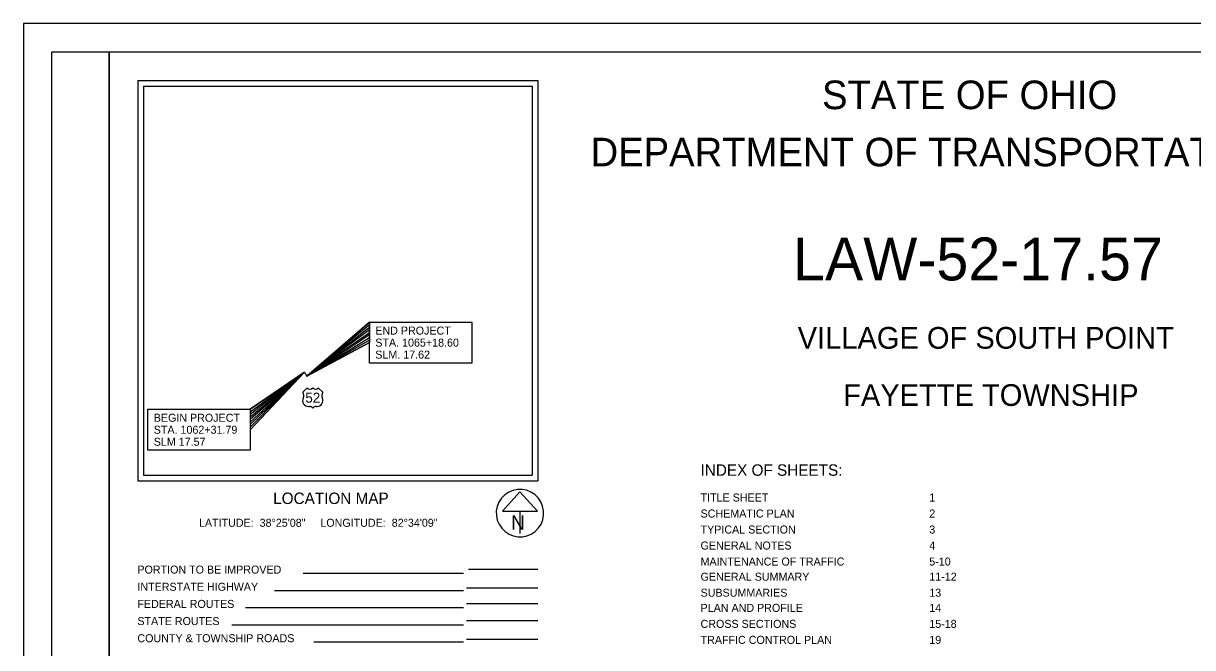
# Model space of a CAD drawing. Extents: x 0 to 34, y 0 to 22.
# Drawn here: x 0 to 20.45, y 11.08 to 22 of the extents above; entities that cross this region are included whole.
import ezdxf

# ---------------------------------------------------------------- set-up
doc = ezdxf.new("R2010")
doc.units = 0
for name, color, linetype in [('GM_X_County_Road', 7, 'Continuous'), ('GM_X_Minor_River', 7, 'Continuous'), ('SH_Border', 7, 'Continuous'), ('SH_Cut_Line', 7, 'Continuous'), ('SH_Data', 7, 'Continuous'), ('SH_Text', 7, 'Continuous')]:
    doc.layers.add(name, color=color, linetype=linetype)

msp = doc.modelspace()

# ---------------------------------------------------------------- linework, layer by layer
at = {"layer": 'GM_X_County_Road'}
for p, q in [((4.958, 15.623), (4.885, 15.55)), ((5.237, 15.55), (5.164, 15.623)), ((4.988, 15.3), (5.002, 15.3)), ((5.12, 15.3), (5.135, 15.3))]:
    msp.add_line(p, q, dxfattribs=at)
for centre, radius, start, end in [((4.801, 15.491), 0.103, 334.5471, 35.0009), ((5.01, 15.676), 0.0735, 225.573, 314.427), ((5.113, 15.676), 0.0735, 225.573, 314.427), ((5.322, 15.491), 0.103, 144.9991, 205.4529), ((4.987, 15.403), 0.103, 154.8319, 270.6383), ((5.136, 15.403), 0.103, 269.3617, 25.1681), ((5.002, 15.227), 0.0735, 36.8699, 90), ((5.12, 15.227), 0.0735, 90, 143.1301)]:
    msp.add_arc(centre, radius, start, end, dxfattribs=at)
at = {"layer": 'GM_X_Minor_River'}
msp.add_lwpolyline([(4.914, 15.902), (4.921, 15.889), (4.936, 15.864), (4.958, 15.829)], dxfattribs=at)
at = {"layer": 'SH_Border'}
for p, q in [((6.053, 16.461), (4.958, 15.829)), ((3.967, 14.938), (4.914, 15.902))]:
    msp.add_line(p, q, dxfattribs=at)
for points in [[(6.053, 16.774), (4.958, 15.829), (6.053, 16.417)], [(6.053, 16.73), (4.958, 15.829), (6.053, 16.685)], [(6.053, 16.64), (4.958, 15.829), (6.053, 16.595)], [(6.053, 16.551), (4.958, 15.829), (6.053, 16.506)], [(3.967, 15.251), (4.914, 15.902), (3.967, 14.893)], [(3.967, 15.206), (4.914, 15.902), (3.967, 15.161)], [(3.967, 15.117), (4.914, 15.902), (3.967, 15.072)], [(3.967, 15.027), (4.914, 15.902), (3.967, 14.982)]]:
    msp.add_lwpolyline(points, dxfattribs=at)
for points in [[(4.958, 15.829), (6.053, 16.774), (6.053, 16.417)], [(6.053, 16.774), (7.843, 16.774), (7.843, 16.059), (6.053, 16.059)], [(3.967, 15.251), (3.967, 14.893), (4.914, 15.902)], [(2.178, 15.251), (3.967, 15.251), (3.967, 14.535), (2.178, 14.535)]]:
    msp.add_lwpolyline(points, close=True, dxfattribs=at)
at = {"layer": 'SH_Cut_Line'}
for p, q in [((2, 21), (9, 21)), ((2, 21), (2, 14)), ((2.1, 20.9), (2.1, 14.1)), ((2.1, 20.9), (8.9, 20.9)), ((8.9, 20.9), (8.9, 14.1)), ((9, 21), (9, 14)), ((2, 14), (9, 14)), ((2.1, 14.1), (8.9, 14.1)), ((2.1, 14.1), (2.1, 14.1)), ((8.685, 13.809), (8.377, 13.468)), ((8.992, 13.468), (8.685, 13.809)), ((8.377, 13.468), (8.992, 13.468)), ((8.685, 13.468), (8.685, 13.081)), ((8.685, 13.435), (8.685, 13.435)), ((8.685, 13.435), (8.685, 13.435)), ((7.7, 12.377), (4.894, 12.377)), ((7.783, 12.455), (9, 12.455)), ((7.7, 12.077), (4.39, 12.077)), ((9, 12.121), (7.75, 12.121)), ((7.7, 11.777), (3.885, 11.777)), ((9, 11.849), (7.75, 11.849)), ((7.7, 11.477), (3.645, 11.477)), ((9, 11.549), (7.75, 11.549)), ((7.7, 11.177), (5.078, 11.177)), ((9, 11.222), (7.75, 11.222))]:
    msp.add_line(p, q, dxfattribs=at)
msp.add_arc((8.685, 13.435), 0.415, 129.7798, 129.7633, dxfattribs=at)
at = {"layer": 'SH_Data'}
for points in [[(0.5, 21.5), (1.5, 21.5), (1.5, 0.5), (0.5, 0.5)], [(1.5, 21.5), (33.5, 21.5), (33.5, 0.5), (1.5, 0.5)]]:
    msp.add_lwpolyline(points, close=True, dxfattribs=at)
at = {"layer": 'SH_Text'}
msp.add_lwpolyline([(0, 0), (34, 0), (34, 22), (0, 22)], close=True, dxfattribs=at)

# ---------------------------------------------------------------- texts
at = {"layer": 'GM_X_County_Road'}
msp.add_text('52', height=0.1763, dxfattribs=at).set_placement((4.931, 15.366))
at = {"layer": 'SH_Border'}
for s, height, p in [('STATE OF OHIO', 0.5, (13.968, 20.5)), ('DEPARTMENT OF TRANSPORTATION', 0.5, (9.92, 19.5)), ('LAW-52-17.57', 0.75, (13.462, 17.505)), ('END PROJECT', 0.14, (6.155, 16.557)), ('VILLAGE OF SOUTH POINT', 0.38, (13.543, 16.31)), ('STA. 1065+18.60', 0.14, (6.155, 16.347)), ('SLM. 17.62', 0.14, (6.155, 16.137)), ('FAYETTE TOWNSHIP', 0.38, (14.338, 15.31)), ('BEGIN PROJECT', 0.14, (2.28, 15.033)), ('STA. 1062+31.79', 0.14, (2.28, 14.823)), ('SLM 17.57', 0.14, (2.28, 14.613)), ('INDEX OF SHEETS:', 0.2, (11.844, 14.088)), ('LOCATION MAP', 0.2, (4.369, 13.594)), ('TITLE SHEET', 0.14, (11.844, 13.638)), ('1', 0.14, (15.844, 13.638)), ('SCHEMATIC PLAN', 0.14, (11.844, 13.358)), ('2', 0.14, (15.844, 13.358)), ('LATITUDE:  38°25\'08"     LONGITUDE:  82°34\'09"', 0.14, (3.071, 13.196)), ('TYPICAL SECTION', 0.14, (11.844, 13.078)), ('3', 0.14, (15.844, 13.078)), ('GENERAL NOTES', 0.14, (11.844, 12.798)), ('4', 0.14, (15.844, 12.798)), ('PORTION TO BE IMPROVED', 0.14, (1.994, 12.377)), ('MAINTENANCE OF TRAFFIC', 0.14, (11.844, 12.518)), ('5-10', 0.14, (15.844, 12.518)), ('GENERAL SUMMARY', 0.14, (11.844, 12.253)), ('11-12', 0.14, (15.844, 12.253)), ('INTERSTATE HIGHWAY', 0.14, (1.994, 12.077)), ('SUBSUMMARIES', 0.14, (11.844, 11.973)), ('13', 0.14, (15.844, 11.973)), ('FEDERAL ROUTES', 0.14, (1.994, 11.777)), ('PLAN AND PROFILE', 0.14, (11.844, 11.708)), ('14', 0.14, (15.844, 11.708)), ('STATE ROUTES', 0.14, (1.994, 11.477)), ('CROSS SECTIONS', 0.14, (11.844, 11.428)), ('15-18', 0.14, (15.844, 11.428)), ('COUNTY & TOWNSHIP ROADS', 0.14, (1.994, 11.177)), ('TRAFFIC CONTROL PLAN', 0.14, (11.844, 11.148)), ('19', 0.14, (15.844, 11.148))]:
    msp.add_text(s, height=height, dxfattribs=at).set_placement(p)
at = {"layer": 'SH_Cut_Line'}
msp.add_text('N', height=0.25, dxfattribs=at).set_placement((8.529, 13.144))

doc.saveas('drawing.dxf')
